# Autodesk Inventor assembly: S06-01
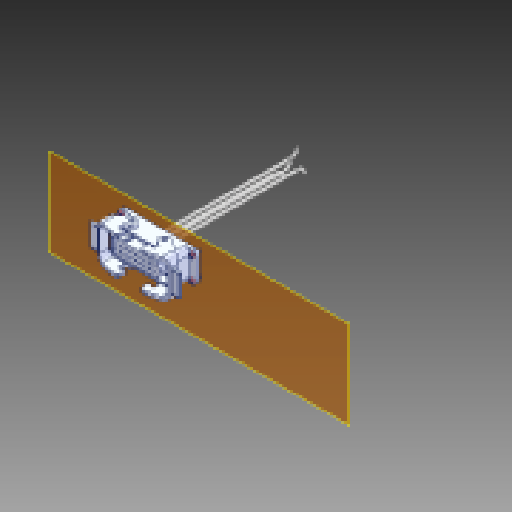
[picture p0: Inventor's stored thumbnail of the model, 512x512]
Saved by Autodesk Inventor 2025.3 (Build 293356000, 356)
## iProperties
Created: 2025-05
Part Number: S06-01
Document SubType Name: Assembly
Designer: Patrik
Description: Elektrická přípojka
Stock Number: E 2710_16B
User Status: Hliník
Sending System: KiM GmbH
Major Version: 4.0
Minor Version: 0.0
Format Version: 0.0
Product Id: KiM GmbH
Hersteller: Meusburger
Material: Aluminiumdruckguss, pulverbeschichtet _ powder coated die-cast aluminium
Bestellnummer: E2710/16B
Teilenummer: E2710/16B
Beschreibung: Steckergehäuse mit zwei Querbügeln _ Connector housing with double locking latch
Author: Patrik
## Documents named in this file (8)
- C:\Users\Patrik\Documents\Skola\Bakalarska prace\Prakticka cast\E 2710_16B.iam
- C:\Users\Patrik\Documents\Skola\Bakalarska prace\Prakticka cast\E 2710_16B.ipt
- C:\Users\Patrik\Documents\Skola\Bakalarska prace\Prakticka cast\E 2710_16B_1.ipt
- C:\Users\Patrik\Documents\Skola\Bakalarska prace\Prakticka cast\E 2710_16B_2.ipt
- C:\Users\Patrik\Documents\Skola\Bakalarska prace\Prakticka cast\E 2710_16B_3.ipt
- C:\Users\Patrik\Documents\Skola\Bakalarska prace\Prakticka cast\E 2710_16B_4.ipt
- C:\Users\Patrik\Documents\Skola\Bakalarska prace\Prakticka cast\E 2700_16B.ipt
- C:\Users\Patrik\Documents\Skola\Bakalarska prace\Prakticka cast\Kabely.ipt
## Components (7 placed, 7 different names)
1. E 2710_16B_1:1 — Vložit:4
2. E 2710_16B_2:1 — Vložit:1, Vložit:2, Vložit:3, Vložit:4, Vložit:5, Vložit:6
3. E 2710_16B_3:1 — Vložit:5
4. E 2710_16B_4:1 — Vložit:3
5. E 2710_16B_5:1 — Vložit:6
6. E 2700_16B:1 — Vložit:1, Vložit:2
7. Kabely:1
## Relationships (6: Insert 6)
- Vložit:1 [Insert]: E 2710_16B_2:1 ↔ E 2700_16B:1
- Vložit:2 [Insert]: E 2710_16B_2:1 ↔ E 2700_16B:1
- Vložit:3 [Insert]: E 2710_16B_2:1 ↔ E 2710_16B_4:1
- Vložit:4 [Insert]: E 2710_16B_1:1 ↔ E 2710_16B_2:1
- Vložit:5 [Insert]: E 2710_16B_2:1 ↔ E 2710_16B_3:1
- Vložit:6 [Insert]: E 2710_16B_2:1 ↔ E 2710_16B_5:1
